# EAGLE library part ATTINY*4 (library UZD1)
8-bit-Mikrocontroller Typmax. TaktFlashRAMEEPROM ATtiny2420 MHz2 kByte128 Byte128 Byte ATtiny24V10 MHz ATtiny4420 MHz4 kByte256 Byte256 Byte ATtiny44V10 MHz ATtiny84V10 MHz8 kByte512 Byte512 Byte
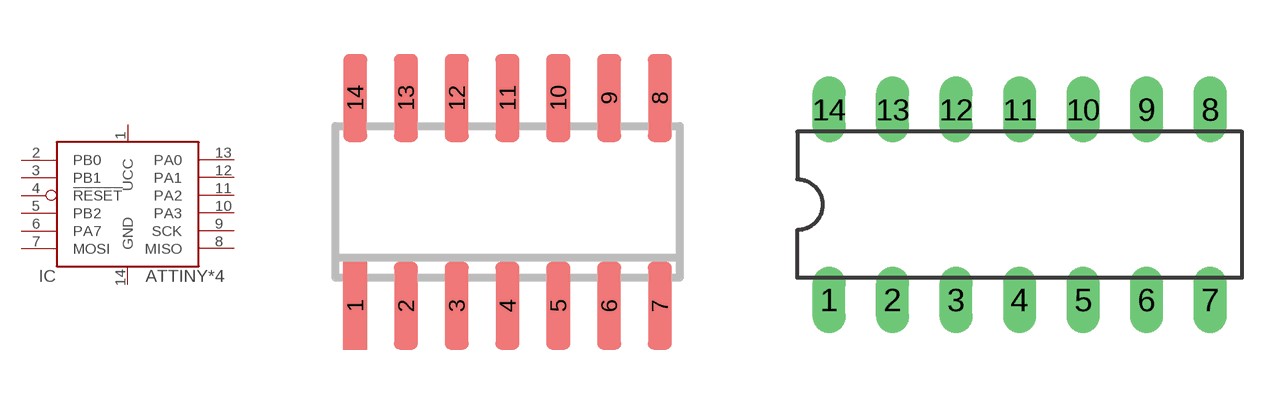
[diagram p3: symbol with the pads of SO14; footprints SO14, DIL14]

Designator prefix IC

## ATTINY24SSU, ATTINY44SSU, ATTINY84SSU  [SO14]
1  UCC  pwr
2  PB0  in
3  PB1
4  !RESET  in
5  PB2
6  PA7  in
7  MOSI  out
8  MISO  in
9  SCK  out
10  PA3  out
11  PA2  out
12  PA1  in
13  PA0  in
14  GND  pwr

## ATTINY24P, ATTINY44P, ATTINY84P  [DIL14]
Pads as for SO14

## Footprint SO14 (pad centres in mm)
Small Outline Package 14
smd 0.6 x 2.2: 1 -3.81,-2.6; 2 -2.54,-2.6; 3 -1.27,-2.6; 4 0,-2.6; 5 1.27,-2.6; 6 2.54,-2.6; 7 3.81,-2.6; 8 3.81,2.6; 9 2.54,2.6; 10 1.27,2.6; 11 0,2.6; 12 -1.27,2.6; 13 -2.54,2.6; 14 -3.81,2.6

## Footprint DIL14 (pad centres in mm)
Dual In Line Package
drill 0.813 long: 1 -7.62,-3.81; 2 -5.08,-3.81; 3 -2.54,-3.81; 4 0,-3.81; 5 2.54,-3.81; 6 5.08,-3.81; 7 7.62,-3.81; 8 7.62,3.81; 9 5.08,3.81; 10 2.54,3.81; 11 0,3.81; 12 -2.54,3.81; 13 -5.08,3.81; 14 -7.62,3.81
